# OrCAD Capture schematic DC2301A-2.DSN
size Custom; title: SINGLE SWITCH TRANSMITTER FOR LTC4123EDC; rev: 2; note: DEMO CIRCUIT2301A
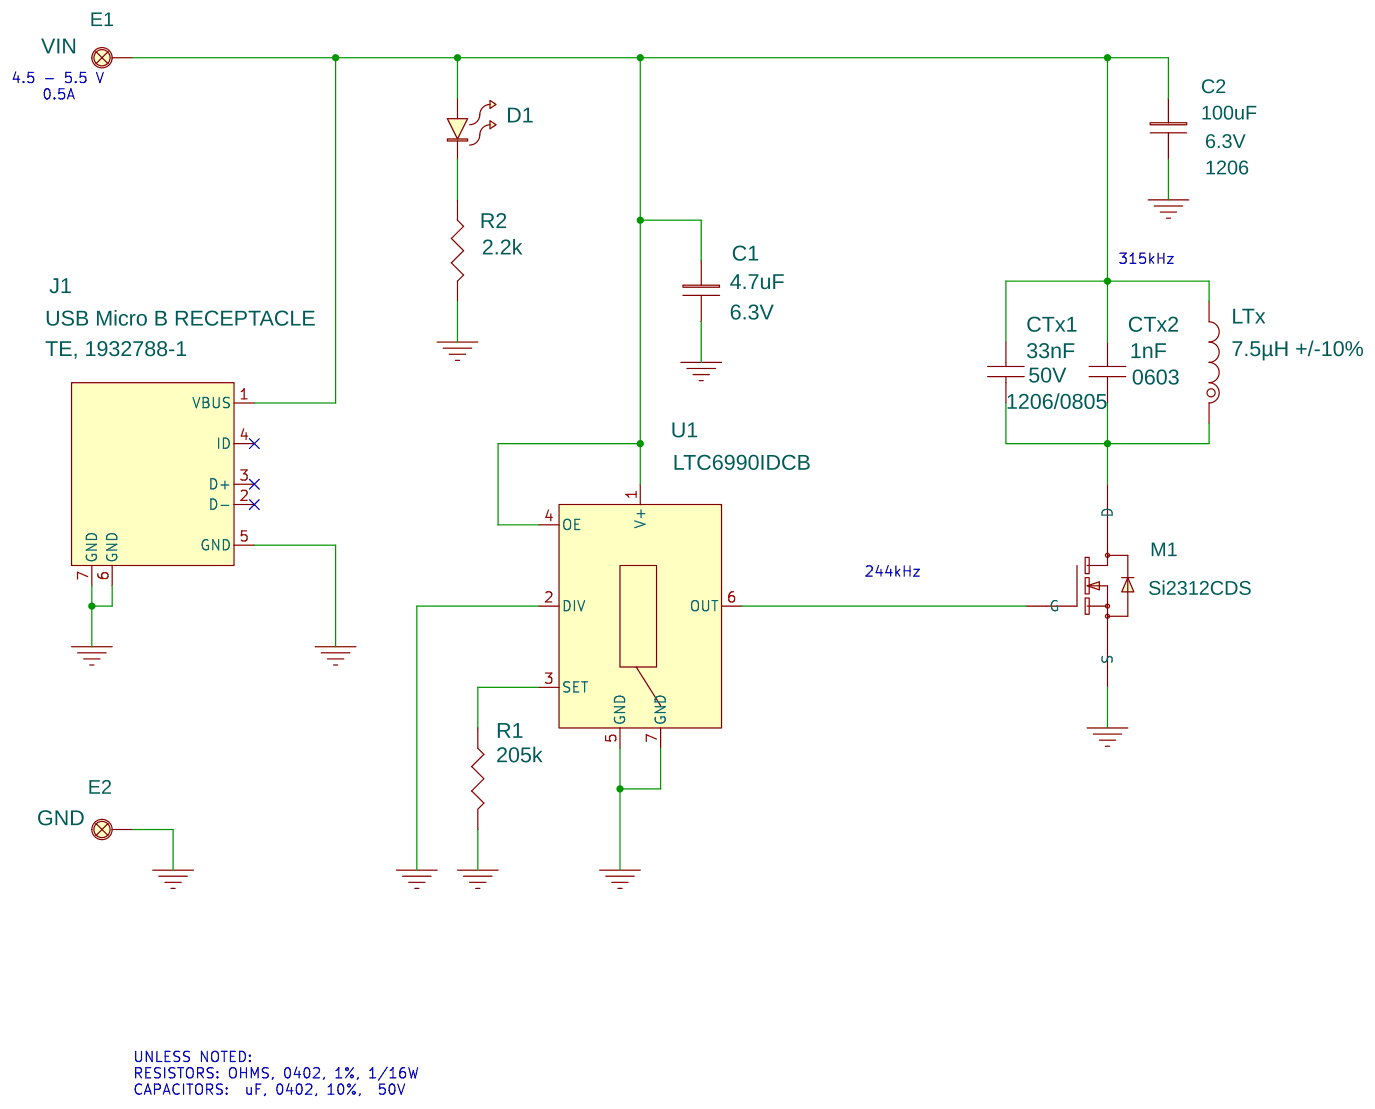
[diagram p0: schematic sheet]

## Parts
C1  4.7uF  [0402-SMALL]
C2  100uF  [1206]
CTx1  33nF  [1206-0805]
CTx2  1nF  [0603]
D1  LTST-C193KRKT-5A  [LED-LTST-C193KRKT-5A]
E1  VIN  [MILL-MAX-2308]
E2  GND  [MILL-MAX-2308]
J1  USB Micro B RECEPTACLE  [MICRO_USB_REVERSE_TYPE_B_TE-1932788]
LTx  7.5µH +/-10%  [LRX-TDK-WR101030-34M8-LT4]
M1  Si2312CDS  [TO-236AB]
R1  205k  [0402-SMALL]
R2  2.2k  [0402-SMALL]
U1  LTC6990IDCB  [DFN6DCB]

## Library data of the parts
C1 = C1005X5R1C474K: VOLTAGE: 6.3V
C2 = C3216X5R1E106K: VOLTAGE: 6.3V
CTx1 = CAP: CAP., 0.1uF, COG, 50V, 5%, 1206; CLASS: DISCRETE; Manufacturer: TDK; Manufacturer PN: C3216C0G1H104J; PART_NUMBER: TMP-1053; Package Size: 1206/0805; Rated Voltage: 50V; Temperature Coefficient: C0G, NP0; Tolerance: 5%
CTx2 = CAP: CAP., 3300pF, NP0, 25V, 5%, 0805; CLASS: DISCRETE; Dielectric Type: NP0; Manufacturer: AVX; Manufacturer PN: 08053A332JAT2A; PART_NUMBER: TMP-36; Rated Voltage: 25V; Tolerance: 5%
D1 = LTST-C193KRKT-5A_2
E1 E2 = TP_KEY_1502-2_0: 4th Part Field: MILL-MAX; 5th Part Field: 2308-2; 7th Part Field: TURRET, SIGNAL; 9th Part Field: EN1; Part Number: MILL-MAX 2308-2
J1 = USB_MINI-B_1: 5th Part Field: TE, 1932788-1
LTx = Transmit_Antenna: WIRELESS CHARGING COIL, WE-WPCC; CLASS: DISCRETE; Manufacturer: Wurth Elektronik; Manufacturer PN: 760308103206; PART_NUMBER: TMP-1032
M1 = Si2306BDS_0: PSpiceTemplate: X^@REFDES %4 %1 %2 @MODEL
R1 = CRCW0402205KFKED
R2 = RES: RES., 2.2k, 1/16W, 5%, 0402; CLASS: DISCRETE; Manufacturer: VISHAY; Manufacturer PN: CRCW04022K20JNED; PART_NUMBER: TMP-259; Package Size: 0402; Rated Power: 1/16W; Tolerance: 5%
U1 = LTC6990CDCB_0

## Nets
GND: C1.2 C2.2 E2.1 J1.5(GND) J1.6(GND) J1.7(GND) M1.2(S) R1.2(pin2) R2.2 U1.2(DIV) U1.5(GND) U1.7(GND)
N12925: C1.1 C2.1 CTx1.1 CTx2.1 D1.1(ANODE) E1.1 J1.1(VBUS) LTx.2 U1.1(V+) U1.4(OE)
N12979: CTx1.2 CTx2.2 LTx.1 M1.3(D)
N13037: R1.1(pin1) U1.3(SET)
N13053: M1.1(G) U1.6(OUT)
N13233: D1.2(CATHODE) R2.1

Not connected (* = marked no-connect by the designer): J1 2(D-)* 3(D+)* 4(ID)*

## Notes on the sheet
- 4.5 - 5.5 V
      0.5A
- 315kHz
- 244kHz
- UNLESS NOTED:
  RESISTORS: OHMS, 0402, 1%, 1/16W
  CAPACITORS:  uF, 0402, 10%,  50V
